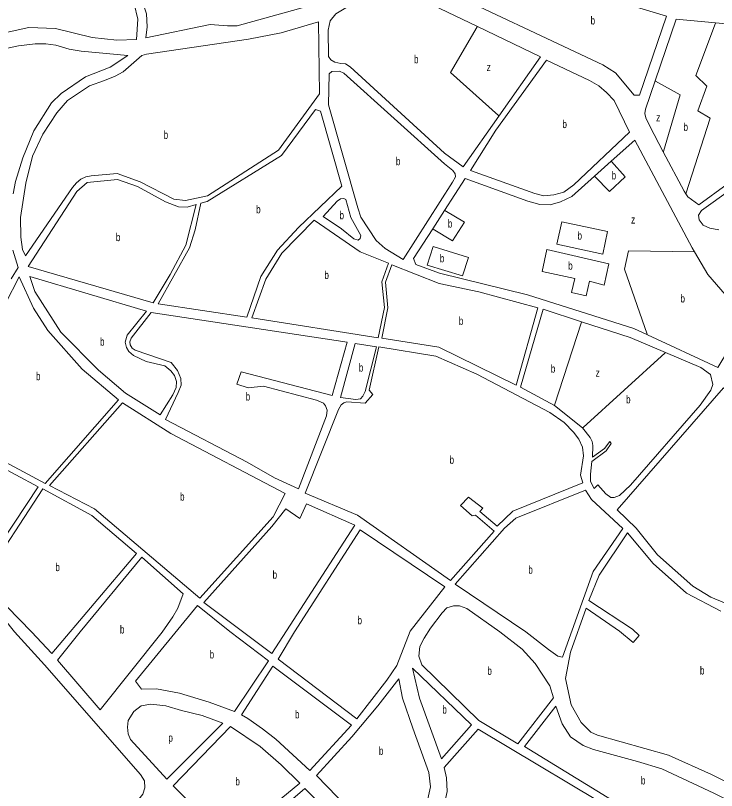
# Model space of a CAD drawing. Extents: x 639657 to 671642, y 222838 to 252123.
# Drawn here: x 646215 to 647091, y 241801 to 242770 of the extents above; entities that cross this region are included whole.
import ezdxf

# ---------------------------------------------------------------- set-up
doc = ezdxf.new("R2010")
doc.units = 0
doc.header["$LTSCALE"] = 4
doc.layers.add('1', color=7, linetype='Continuous', lineweight=13)
doc.layers.add('21', color=7, linetype='Continuous', lineweight=13)
doc.layers.add('7', color=7, linetype='Continuous')

msp = doc.modelspace()

# ---------------------------------------------------------------- linework, layer by layer
at = {"layer": '1'}
for p, q in [((647134.57, 242756.69), (647090.209, 242760.748)), ((646983.73, 242367.51), (646922.865, 242387.181))]:
    msp.add_line(p, q, dxfattribs=at)
for points in [[(646356.86, 242954.26), (646285.86, 242996.19), (646221.45, 242877.12), (646350.83, 242816.3), (646359.62, 242811.54), (646372.67, 242792.58), (646379.04, 242771.71), (646379.85, 242755.81), (646378.51, 242741.84), (646458.73, 242758.76), (646480.21, 242756.76), (646492.25, 242756.93), (646596.36, 242785.8), (646648.44, 242808.82), (646651.67, 242811.61), (646653.62, 242815.68), (646652.56, 242818.91), (646648.92, 242823.22), (646378.74, 242941.51)], [(646995.42, 242670.17), (647028.87, 242769.14), (646794.19, 242839.67), (646795.5, 242846.97), (646739.77, 242826.75), (646731.76, 242811.09), (646949.56, 242708.18), (646965.43, 242698.23), (646988.54, 242670.41)], [(646286.62, 242554.84), (646227.85, 242469.45), (646224.01, 242477.42), (646221.92, 242492.7), (646221.79, 242517.42), (646228.18, 242560.19), (646236.69, 242593.92), (646249.68, 242621.4), (646266.97, 242648.21), (646280.56, 242663.44), (646307.92, 242682.05), (646326.64, 242688.44), (646339.99, 242693.99), (646349.89, 242699.54), (646373.17, 242719.89), (646378.98, 242721.38), (646506.5, 242740.3), (646547.36, 242748.11), (646594.26, 242761.92), (646595.24, 242671.85), (646544.05, 242601.73), (646455.51, 242544.62), (646427.76, 242538.69), (646413.37, 242540.46), (646371.11, 242562.1), (646342.35, 242572.3), (646309.89, 242569.61), (646303.22, 242568.34), (646297.19, 242565.35), (646291.59, 242560.85)], [(646932.94, 242688.68), (646879.08, 242713.82), (646815.58, 242626.35), (646784.02, 242575.94), (646864.51, 242547.27), (646875.67, 242544.43), (646888.36, 242545.89), (646900.84, 242549.07), (646913.33, 242558.27), (646982.79, 242624), (646963.37, 242663.42), (646954.17, 242673.77), (646944.52, 242681.76)], [(646677.26, 242478.72), (646699.99, 242465.09), (646761.61, 242561.62), (646765.29, 242568.06), (646764.88, 242572.14), (646762.1, 242576.02), (646751.38, 242584.45), (646625.63, 242697.76), (646620.48, 242700.35), (646610.81, 242699.96), (646607.57, 242696.74), (646606.79, 242658.27), (646643.07, 242529.36), (646647.11, 242517.74), (646666.13, 242488.64)], [(646393.74, 242409.58), (646504.57, 242392.87), (646521.96, 242443.56), (646542.93, 242476.39), (646569.26, 242504.68), (646623.19, 242556.52), (646596.66, 242650.35), (646590.22, 242652.3), (646547.68, 242594.83), (646455.05, 242537.53), (646447.09, 242535.19), (646440.09, 242501.89), (646432.91, 242479.55)], [(646387.3, 242410.89), (646231.45, 242456.11), (646292.19, 242549.67), (646305.13, 242561.24), (646342.75, 242564.77), (646367.86, 242556.3), (646403.04, 242536.84), (646419.35, 242530.77), (646429.88, 242530.3), (646441.07, 242533.49), (646428.41, 242482.79), (646408.71, 242446.3)], [(646628.28, 242539.73), (646625.92, 242541.25), (646621.62, 242540.62), (646617.53, 242537.83), (646599.83, 242518.55), (646622.99, 242503.42), (646638.2, 242490.89), (646643.78, 242489.15), (646646.15, 242491.29), (646647.02, 242494.73), (646634.64, 242517.35)], [(646681.77, 242460.34), (646646.09, 242474.31), (646588.64, 242513.86), (646548.08, 242472.71), (646528.39, 242440.31), (646510.58, 242391.99), (646668.79, 242367.16), (646676.56, 242404.95), (646673.25, 242437.12)], [(646744.47, 242355.27), (646673.34, 242366.44), (646680.89, 242404.56), (646677.82, 242436.48), (646685.82, 242458.42), (646744.79, 242434.83), (646794.4, 242424.55), (646868.25, 242404.28), (646840.99, 242308.05)], [(646238.12, 242404.05), (646220.22, 242443.03), (646202.9, 242409.76), (646200.3, 242350.63), (646152.81, 242297.87), (646120.62, 242255.6), (646252.49, 242185.09), (646344.04, 242289.32), (646298.64, 242327.74), (646256.06, 242376.05)], [(646379.3, 242400.38), (646233.33, 242443.85), (646239.71, 242424.91), (646271.96, 242374.28), (646319.05, 242326.6), (646352.89, 242297.68), (646396.4, 242270.66), (646412.19, 242295.77), (646416.1, 242305), (646416.56, 242312.31), (646414.23, 242319.85), (646409.74, 242325.88), (646402.24, 242331.93), (646378.62, 242337.59), (646362.75, 242344.96), (646357.18, 242349.71), (646353.98, 242354.88), (646352.29, 242361.76), (646355.11, 242370.14)], [(646629.71, 242361.39), (646384.89, 242398.86), (646360.04, 242366.47), (646358.31, 242362.17), (646358.72, 242358.09), (646361.07, 242353.99), (646365.14, 242351.62), (646409.78, 242335.99), (646417.91, 242326.28), (646422.16, 242316.16), (646422.56, 242307.78), (646418.87, 242298.54), (646402.83, 242265.05), (646504.9, 242211.81), (646539.2, 242192.12), (646569.23, 242178.47), (646604, 242269.54), (646604.89, 242276.41), (646602.98, 242282.01), (646600.41, 242285.25), (646591.4, 242288.93), (646525.28, 242306.57), (646506.15, 242304.7), (646492.2, 242309.27), (646497.42, 242324.3), (646611.05, 242295.07)], [(646619.29, 242277.44), (646577.58, 242172.85), (646642.8, 242145.32), (646759.13, 242063.61), (646813.56, 242125.57), (646790.44, 242145.23), (646785.92, 242144.38), (646771.58, 242157.34), (646781.73, 242168.05), (646799.5, 242154.01), (646795.62, 242149.94), (646817.46, 242131.58), (646837.09, 242150.22), (646924.5, 242185.6), (646921.32, 242195.5), (646925.08, 242219.57), (646924.05, 242230.33), (646919.58, 242240.45), (646912.96, 242249.29), (646900.97, 242261.38), (646882.97, 242273.49), (646791.83, 242321.77), (646740.78, 242343.89), (646669.69, 242355.54), (646657.43, 242301.39), (646662.14, 242296.21), (646652.21, 242285.5), (646629.65, 242287.08), (646625.77, 242285.59), (646622.54, 242283.23)], [(646621.6, 242292.36), (646640.83, 242289.84), (646646.64, 242290.68), (646649.66, 242293.89), (646652.27, 242299.9), (646666.46, 242355.76), (646639.95, 242359.82)], [(647310.46, 241918.95), (647298.5, 242000.26), (647279.76, 242138.84), (647226.05, 242143.14), (647197.29, 242152.07), (647182.5, 242159.01), (647176.93, 242164.2), (647173.09, 242171.31), (647154, 242227.94), (647145.27, 242247.54), (647134.18, 242266.73), (647100.38, 242304.49), (646967.34, 242152.1), (646991.09, 242129.22), (647017.81, 242096), (647061.68, 242056.47), (647084.4, 242042.83), (647184.75, 242001.31), (647296.73, 241916.75), (647303.17, 241916.13)], [(646537.48, 242143.31), (646552.44, 242172.51), (646409.42, 242247.39), (646349.18, 242285.65), (646258.06, 242182.28), (646314.24, 242153.28), (646445.7, 242041.45)], [(646103.86, 242255.65), (646040.29, 242164.01), (646131.12, 242097.71), (646167.95, 242066.84), (646243.66, 242180.6)], [(646261.05, 241972.7), (646235.55, 241999.74), (646173.73, 242062.31), (646249.45, 242178.22), (646310.98, 242145.12), (646366.86, 242097.41)], [(646881.61, 241977.57), (646853.32, 241999.61), (646764.69, 242059.29), (646826.69, 242128.96), (646840.71, 242141.82), (646927.69, 242176.77), (646935.37, 242165.12), (646974.33, 242128.85), (646937.34, 242075.01), (646898.82, 241967.74), (646893.24, 241969.24)], [(646535.7, 241972.53), (646639.52, 242132.85), (646579.25, 242159.51), (646570.79, 242141.26), (646553.43, 242153.15), (646535.93, 242131.27), (646450.61, 242036.38)], [(646564.13, 241999.76), (646543.89, 241965.26), (646642.15, 241890.96), (646679.51, 241939.19), (646692.09, 241957.49), (646708.708, 242000.332), (646752, 242055.68), (646646.16, 242127.24)], [(645858.47, 241865.89), (646093.56, 242109.01), (646187.78, 242031.94), (646214.33, 241999.51), (646251.88, 241958.28), (646371.69, 241821.18), (646376.66, 241813.26), (646376.91, 241804.46), (646374.59, 241796.51), (646367.97, 241788.32), (646163.68, 241565.33)], [(646296.37, 241999.56), (646267.96, 241964.14), (646321.29, 241902.11), (646398.58, 241999.23), (646412.07, 242018.33), (646418.14, 242029.07), (646425.09, 242047.11), (646373.29, 242092.87)], [(646442.86, 242032.64), (646365.57, 241937.92), (646372.92, 241927.87), (646391.6, 241928.37), (646420.4, 241922.91), (646457.6, 241911.89), (646489.22, 241900), (646531.45, 241963.28), (646483.12, 242000.03)], [(646726.29, 241991.75), (646733.96, 242004.02), (646748.63, 242023.21), (646754.67, 242029.64), (646762.64, 242031.98), (646770.16, 242031.96), (646779.38, 242028.7), (646820.74, 241999.65), (646848.75, 241977.86), (646864.94, 241959.9), (646883.32, 241932.07), (646887.89, 241917.27), (646843.28, 241859.78), (646794.4, 241888.78), (646723.23, 241958.47), (646719.31, 241969.19), (646720.76, 241981.21)], [(646497.83, 241895.96), (646537.06, 241956.86), (646635.31, 241882.99), (646583.18, 241826.11), (646540.7, 241865.44), (646524.1, 241878.25), (646505.79, 241891.27)], [(646720.41, 241916.6), (646711.44, 241954.13), (646785.19, 241883.16), (646747.81, 241840.72)], [(646668.06, 241907.16), (646694.53, 241940.75), (646699.15, 241916.52), (646711.78, 241879), (646731.99, 241823.92), (646734.01, 241805.89), (646730.01, 241786.99), (646718.5, 241768.27), (646701.81, 241755.32), (646680.36, 241750.94), (646661.01, 241755.16), (646644.21, 241766.04), (646591.58, 241820.13), (646635.81, 241868.18)], [(646404.57, 241815.3), (646474.68, 241885.56), (646448.87, 241895.12), (646422.86, 241901.24), (646403.29, 241906.95), (646384.6, 241909.24), (646372.58, 241907.04), (646363.38, 241899.92), (646356.13, 241888.73), (646355.53, 241880.36), (646356.21, 241871.99), (646359.03, 241865.13)], [(646898.78, 241884.47), (646890.73, 241906.76), (646851.67, 241856.38), (646993.56, 241769.36), (647085.07, 241710.9), (647142.52, 241733.24), (647165.65, 241746), (647174.85, 241754.84), (647087.91, 241798.07), (647022.93, 241828.3), (646992.61, 241837.62), (646937.79, 241852.64), (646924.88, 241857.74), (646909.16, 241868.41)], [(646521.2, 241856.13), (646484.15, 241881.31), (646412.55, 241806.96), (646441.89, 241777.46), (646478.15, 241734.03), (646570.58, 241810.39), (646547.28, 241833.48)], [(646751.08, 241830.22), (646793.59, 241878.04), (646983.27, 241764.6), (647077.37, 241703.79), (647050.14, 241646.36), (647040.52, 241637.31), (646956.2, 241574.08), (646750.44, 241779.56), (646754.86, 241799.97), (646753.93, 241817.13)], [(646485.28, 241725.26), (646576.83, 241803.97), (646667.21, 241714.18), (646587.43, 241593), (646544.09, 241635.55), (646526.81, 241658.66), (646511.01, 241685)]]:
    msp.add_lwpolyline(points, close=True, dxfattribs=at)
for points in [[(646199.91, 242747.79), (646231.96, 242754.99), (646265.48, 242753.38), (646311.43, 242742.26), (646341.94, 242738.94), (646366.65, 242739.71), (646368.46, 242765.29), (646363.59, 242784.22), (646352.03, 242799.74), (646341.75, 242808.16), (646035.73, 242947.36)], [(646792.629, 242756.062), (646708.07, 242796.78), (646699.27, 242799.6), (646684.45, 242801.37), (646677.35, 242800.54), (646667.24, 242796.92), (646628.06, 242779.43), (646615.57, 242771.95), (646608.66, 242763.17), (646606.26, 242751.57), (646606.58, 242718.67), (646609.35, 242714.37), (646614.5, 242711.55), (646621.8, 242709.81), (646628.04, 242709.36), (646633.83, 242705.47), (646751.43, 242597.77)], [(647090.209, 242760.748), (647040.903, 242765.258), (647014.806, 242688.176)], [(646819.601, 242644.199), (646871.36, 242718.15), (646792.629, 242756.062)], [(646212.66, 242547.12), (646215.51, 242562.38), (646224.43, 242591.81), (646238.52, 242625.52), (646260.57, 242660.7), (646272.64, 242672.28), (646302.8, 242693.25), (646333.58, 242705.19), (646355.98, 242719.95), (646297.33, 242725.3), (646282.51, 242727.71), (646265.76, 242732.71), (646253.3, 242734.25), (646239.97, 242734.29), (646219.33, 242731.99), (646150.3, 242717.37)], [(647014.806, 242688.176), (647002.88, 242652.95), (647002, 242647.15), (647003.27, 242641.98), (647007.96, 242631.64), (647024.915, 242599.461)], [(646751.43, 242597.77), (646775.01, 242580.49), (646819.601, 242644.199)], [(647064.011, 242474.655), (647061.12, 242479.66), (646989.2, 242614.09), (646959.782, 242587.688), (646938.893, 242568.94)], [(647024.915, 242599.461), (647050.86, 242550.22), (647053.315, 242546.77)], [(647053.315, 242546.77), (647055.77, 242543.32), (647069.27, 242533.38), (647140.39, 242584.69), (647149.87, 242590.24), (647157.62, 242593.44), (647166.44, 242595.34), (647179.13, 242596.58), (647182.005, 242596.665)], [(647143.16, 242576.73), (647072.9, 242526.05), (647068.8, 242520.48), (647069.63, 242514.46), (647074.76, 242507.99), (647083.13, 242504.08), (647094.3, 242502.1)], [(646855.66, 242537.63), (646777.32, 242566.08), (646751.669, 242526.284), (646736.863, 242503.312)], [(646938.893, 242568.94), (646910.48, 242543.44), (646896.71, 242536.83), (646883.58, 242533.22), (646870.69, 242533.7), (646855.66, 242537.63)], [(646736.863, 242503.312), (646712.89, 242466.12), (646715.66, 242458.58), (646745.27, 242447.73), (646855.2, 242420.88), (646988.28, 242378.67), (647005.043, 242370.874)], [(646210.11, 242440.7), (646218.76, 242455.08), (646211.97, 242476.6)], [(647005.043, 242370.874), (647093.18, 242329.89), (647133.21, 242396.17), (647116.71, 242408.71), (647102.36, 242421.02), (647080.54, 242446.04), (647064.011, 242474.655)], [(646922.865, 242387.181), (646874.69, 242402.75), (646846.57, 242305.23), (646889.03, 242282.5), (646924.15, 242254.41)], [(646924.15, 242254.41), (646933.56, 242242.33), (646935.9, 242237.59), (646936.74, 242232.43), (646936.68, 242218.02), (646951.55, 242228.72), (646958.04, 242237.51), (646959.96, 242235.14), (646953.47, 242225.92), (646935.79, 242212.65), (646933.79, 242196.74), (646934.18, 242187.49), (646938.66, 242178.66), (646942.97, 242183.16), (646953.03, 242171.94), (646959.24, 242167.4), (646963.75, 242167.38), (646970.21, 242170.16), (646983.81, 242183.01), (647071.06, 242282.67), (647084.25, 242301.75), (647086.86, 242308.63), (647084.12, 242321.11), (647071.69, 242329.97), (647027.662, 242348.761), (646983.73, 242367.51)], [(647189.6, 241769.28), (647085.01, 241821.24), (647031.65, 241845.5), (646942.86, 241870.27), (646934.47, 241874.31), (646922.39, 241886.07), (646909.84, 241908.56), (646902.6, 241941.16), (646908.95, 241974.16), (646928.74, 242029.01), (646970.03, 242000.54), (646987.43, 241986.36), (646994.69, 241995.19), (646986.36, 242003), (646932.01, 242038.68), (646944.84, 242070.25), (646980.32, 242123.24), (647012.17, 242085.05), (647053.91, 242048.11), (647096.79, 242025.58)]]:
    msp.add_lwpolyline(points, dxfattribs=at)
at = {"layer": '21'}
for points in [[(647053.315, 242546.77), (647083.696, 242641.493), (647068.318, 242650.585), (647079.502, 242681.355), (647065.522, 242694.643), (647090.022, 242760.248), (647090.209, 242760.748)], [(646819.601, 242644.199), (646819.101, 242644.649), (646759.098, 242698.678), (646792.337, 242755.562), (646792.629, 242756.062)], [(647014.806, 242688.176), (647015.306, 242687.898), (647045.95, 242670.865), (647025.062, 242599.961), (647024.915, 242599.461)], [(646938.893, 242568.94), (646939.393, 242568.44), (646957.901, 242549.922), (646977.113, 242568.308), (646960.229, 242587.187), (646959.782, 242587.688)], [(646751.669, 242526.284), (646752.169, 242525.988), (646776.639, 242511.48), (646761.604, 242488.08), (646737.363, 242503.004), (646736.863, 242503.312)], [(647005.043, 242370.874), (647004.868, 242371.375), (646976.278, 242452.98), (646981.289, 242475.545), (647063.511, 242474.66), (647064.011, 242474.655)], [(646889.03, 242282.5), (646889.192, 242283), (646922.703, 242386.681), (646922.865, 242387.181)], [(646924.15, 242254.41), (646924.65, 242254.866), (647027.162, 242348.305), (647027.662, 242348.761)]]:
    msp.add_lwpolyline(points, dxfattribs=at)
for points in [[(646898.289, 242512.158), (646891.912, 242483.902), (646949.548, 242471.366), (646955.395, 242499.78)], [(646737.537, 242481.034), (646729.862, 242457.995), (646774.133, 242444.623), (646781.651, 242467.187)], [(646873.742, 242449.808), (646879.382, 242477.216), (646957.065, 242459.666), (646951.218, 242432.924), (646932.842, 242437.938), (646928.665, 242419.552), (646910.288, 242423.731), (646914.465, 242441.281)]]:
    msp.add_lwpolyline(points, close=True, dxfattribs=at)

# ---------------------------------------------------------------- texts
at = {"layer": '7'}
for s, width, p in [('b', 0.75, (646934.106, 242758.57)), ('b', 0.75, (646713.418, 242710.151)), ('z', 0.8, (646804.204, 242700.349)), ('z', 0.8, (647015.973, 242637.43)), ('b', 0.75, (646898.93, 242629.125)), ('b', 0.75, (647050.224, 242625.541)), ('b', 0.75, (646400.608, 242615.685)), ('b', 0.75, (646690.816, 242582.72)), ('b', 0.75, (646960.407, 242564.965)), ('b', 0.75, (646516.164, 242522.585)), ('b', 0.75, (646620.387, 242515.2)), ('b', 0.75, (646755.756, 242504.794)), ('z', 0.8, (646984.631, 242509.808)), ('b', 0.75, (646340.856, 242487.83)), ('b', 0.75, (646917.806, 242489.752)), ('b', 0.75, (646745.733, 242461.338)), ('b', 0.75, (646906.112, 242452.145)), ('b', 0.75, (646601.503, 242440.51)), ('b', 0.75, (647046.443, 242411.195)), ('b', 0.75, (646769.477, 242383.235)), ('b', 0.75, (646321.085, 242357.255)), ('b', 0.75, (646644.518, 242324.83)), ('b', 0.75, (646884.394, 242323.446)), ('b', 0.75, (646241.094, 242314.06)), ('z', 0.8, (646940.359, 242318.432)), ('b', 0.75, (646503.095, 242288.665)), ('b', 0.75, (646978.477, 242285.065)), ('b', 0.75, (646757.872, 242209.575)), ('b', 0.75, (646421.097, 242163.55)), ('b', 0.75, (646265.278, 242075.46)), ('b', 0.75, (646856.289, 242072.255)), ('b', 0.75, (646536.751, 242066.02)), ('b', 0.75, (646642.853, 242009.1)), ('b', 0.75, (646345.952, 241997.49)), ('b', 0.75, (646458.098, 241966.32)), ('b', 0.75, (646805.143, 241945.88)), ('b', 0.75, (647070.751, 241946.26)), ('b', 0.75, (646748.85, 241897.425)), ('b', 0.75, (646564.718, 241891.485)), ('p', 0.75, (646406.542, 241862.27)), ('b', 0.75, (646669.598, 241845.845)), ('b', 0.75, (646490.261, 241807.67)), ('b', 0.75, (646996.992, 241808.83))]:
    msp.add_text(s, height=10, dxfattribs=dict(at, width=width)).set_placement(p)

doc.saveas('drawing.dxf')
